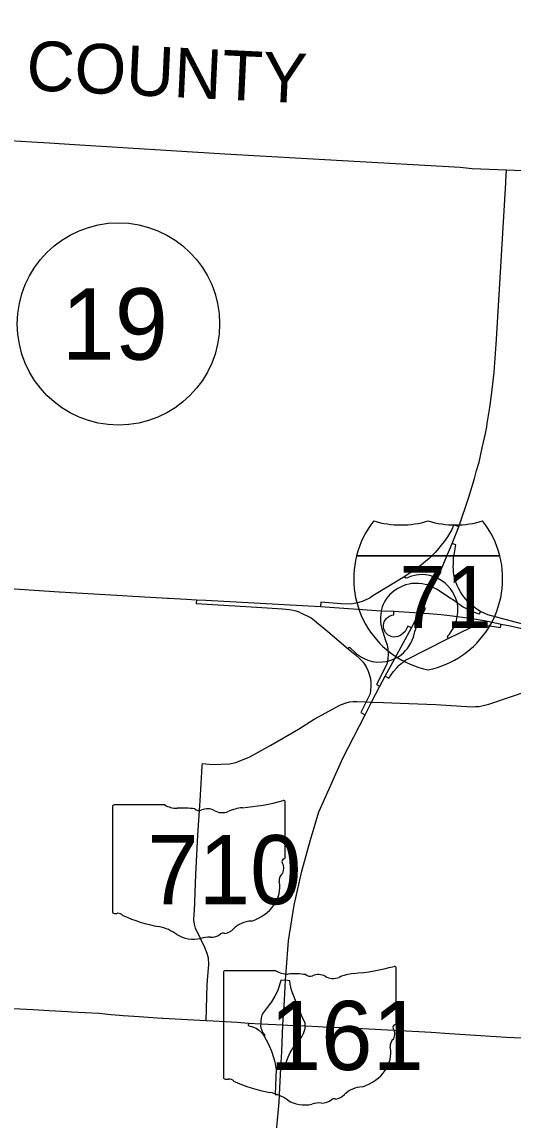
# Model space of a CAD drawing. Extents: x -1146 to -445, y -1283 to -822.
# Drawn here: x -887.8 to -863.1, y -948.4 to -893.1 of the extents above; entities that cross this region are included whole.
import ezdxf

# ---------------------------------------------------------------- set-up
doc = ezdxf.new("R2010")
doc.units = 0
for name, color, linetype in [('Default', 7, 'Continuous'), ('GM_X_Adjacent_County_Text', 7, 'Continuous'), ('GM_X_County', 7, 'Continuous'), ('GM_X_Interchange_Ramps', 7, 'Continuous'), ('GM_X_Interstate_Route', 7, 'Continuous'), ('GM_X_Interstate_Shield', 7, 'Continuous'), ('GM_X_State_Route', 7, 'Continuous'), ('GM_X_State_Shield', 7, 'Continuous')]:
    doc.layers.add(name, color=color, linetype=linetype)

msp = doc.modelspace()

# ---------------------------------------------------------------- linework, layer by layer
at = {"layer": 'Default'}
msp.add_circle((-882.968, -908.344), 5.094, dxfattribs=at)
at = {"layer": 'GM_X_County'}
msp.add_lwpolyline([(-889, -899.078), (-887.326, -899.166), (-886.456, -899.216), (-885.188, -899.314), (-877.604, -899.779), (-865.764, -900.453), (-865.165, -900.518), (-863.427, -900.578), (-862.623, -900.623)], dxfattribs=at)
at = {"layer": 'GM_X_Interchange_Ramps'}
for points in [[(-865.828, -918.558), (-866.078, -918.459), (-866.204, -918.728), (-866.401, -919.059), (-866.562, -919.295), (-866.716, -919.488), (-866.846, -919.654), (-867, -919.835), (-867.177, -920.012), (-867.326, -920.158), (-867.516, -920.315), (-867.712, -920.481), (-868.075, -920.737), (-868.547, -921.067), (-870.161, -922.04), (-870.296, -922.131), (-870.387, -922.183), (-870.51, -922.246), (-870.586, -922.279), (-870.696, -922.322), (-870.809, -922.358), (-870.911, -922.385), (-871.009, -922.406), (-871.103, -922.421), (-871.258, -922.453), (-871.76, -922.444), (-872.777, -922.362), (-872.795, -922.571)], [(-862.612, -923.457), (-863.25, -923.291), (-864.377, -922.994), (-864.744, -922.819), (-864.87, -922.744), (-864.977, -922.67), (-865.062, -922.607), (-865.162, -922.525), (-865.285, -922.414), (-865.377, -922.32), (-865.483, -922.202), (-865.57, -922.093), (-865.66, -921.966), (-865.746, -921.831), (-865.827, -921.684), (-865.908, -921.511), (-865.958, -921.387), (-866.005, -921.251), (-866.05, -921.094), (-866.077, -920.976), (-866.094, -920.823), (-866.098, -920.697), (-866.113, -920.571), (-866.106, -920.433), (-866.106, -920.288), (-866.09, -920.126), (-866.07, -919.973), (-865.973, -919.464), (-866.167, -919.406)], [(-866.359, -924.181), (-866.399, -924.069), (-866.304, -923.974), (-866.209, -923.84), (-866.113, -923.689), (-865.996, -923.46), (-865.946, -923.281), (-865.912, -923.079), (-865.873, -922.873), (-865.879, -922.61), (-865.901, -922.403), (-866.002, -922.123), (-866.147, -921.833), (-866.242, -921.682), (-866.415, -921.508), (-866.522, -921.391), (-866.728, -921.245), (-866.907, -921.145), (-867.086, -921.078), (-867.282, -921.011), (-867.5, -920.972), (-867.673, -920.96), (-867.841, -920.972), (-867.981, -920.988), (-868.256, -921.067), (-868.421, -921.123), (-868.496, -921.154), (-868.547, -921.067)], [(-864.744, -922.819), (-864.822, -922.956), (-865.074, -922.856), (-865.208, -922.794), (-865.426, -922.694), (-865.605, -922.604), (-865.717, -922.537), (-865.901, -922.403), (-866.055, -922.295), (-866.262, -922.148), (-866.958, -921.698), (-867.154, -921.597), (-867.284, -921.543), (-867.428, -921.485), (-867.525, -921.464), (-867.669, -921.428), (-867.838, -921.41), (-868.003, -921.41), (-868.194, -921.424), (-868.338, -921.446), (-868.518, -921.489), (-868.734, -921.579), (-868.899, -921.662), (-869.036, -921.744), (-869.187, -921.863), (-869.32, -921.982), (-869.475, -922.176), (-869.558, -922.313), (-869.644, -922.478), (-869.687, -922.59), (-869.734, -922.784), (-869.756, -922.964), (-869.774, -923.122), (-869.774, -923.327), (-869.764, -923.474), (-869.73, -923.637), (-869.519, -924.279), (-869.446, -924.508), (-869.407, -924.72), (-869.384, -924.983), (-869.407, -925.212), (-869.422, -925.322), (-869.463, -925.486), (-869.969, -926.498), (-869.804, -926.591)], [(-879.041, -922.231), (-879.057, -922.417), (-876.007, -922.607), (-874.715, -922.686), (-874.369, -922.726), (-874.164, -922.765), (-874.03, -922.796), (-873.888, -922.847), (-873.764, -922.902), (-873.494, -923.025), (-873.266, -923.151), (-873.092, -923.277), (-872.431, -923.836), (-871.403, -924.703), (-871.048, -924.998), (-870.82, -925.203), (-870.682, -925.345), (-870.584, -925.479), (-870.477, -925.644), (-870.391, -925.825), (-870.336, -925.983), (-870.28, -926.215), (-870.253, -926.396), (-870.253, -926.589), (-870.269, -926.782), (-870.299, -926.967), (-870.492, -927.382), (-870.756, -927.913), (-870.546, -928.025)], [(-871.403, -924.703), (-871.334, -924.623), (-870.974, -924.957), (-870.726, -925.127), (-870.555, -925.216), (-870.411, -925.275), (-870.192, -925.342), (-869.958, -925.375), (-869.673, -925.364), (-869.495, -925.342), (-869.422, -925.322), (-869.243, -925.272), (-869.052, -925.189), (-868.824, -925.075), (-868.62, -924.905), (-868.509, -924.797), (-868.422, -924.684), (-868.241, -924.413), (-868.119, -924.115), (-868.037, -923.825), (-867.932, -923.513), (-867.735, -923.132), (-867.627, -922.907), (-867.5, -922.656), (-867.675, -922.606)], [(-868.218, -923.643), (-868.398, -923.559), (-868.536, -923.835), (-868.744, -924.012), (-868.803, -924.048), (-868.904, -924.09), (-869.002, -924.11), (-869.105, -924.112), (-869.204, -924.096), (-869.306, -924.059), (-869.386, -924.013), (-869.469, -923.942), (-869.515, -923.887), (-869.563, -923.809), (-869.605, -923.701), (-869.623, -923.602), (-869.624, -923.519), (-869.609, -923.421), (-869.583, -923.341), (-869.541, -923.259), (-869.479, -923.177), (-869.422, -923.123), (-869.375, -923.088), (-869.317, -923.054), (-869.195, -923.013), (-869.107, -923.001), (-869.097, -922.805)], [(-869.534, -926.081), (-869.358, -926.189), (-869.115, -925.84), (-868.957, -925.669), (-868.826, -925.525), (-868.661, -925.387), (-868.523, -925.282), (-866.359, -924.181), (-865.219, -923.627), (-865.029, -923.577), (-864.911, -923.543), (-864.805, -923.532), (-864.67, -923.514), (-864.473, -923.527), (-864.268, -923.54), (-863.727, -923.639), (-863.692, -923.463)], [(-874.554, -941.397), (-874.79, -941.404), (-874.875, -941.691), (-874.967, -941.942), (-875.102, -942.204), (-875.269, -942.476), (-875.531, -942.831), (-875.676, -943.039), (-875.742, -943.16), (-875.785, -943.298), (-875.798, -943.44), (-875.805, -943.584)], [(-873.568, -943.696), (-873.562, -943.547), (-873.661, -943.358), (-873.811, -943.006), (-874.016, -942.504), (-874.177, -942.115), (-874.254, -941.902), (-874.293, -941.744), (-874.324, -941.599), (-874.343, -941.429), (-874.554, -941.397)], [(-876.427, -943.552), (-876.436, -943.682), (-876.215, -943.736), (-876.037, -943.814), (-875.893, -943.914), (-875.755, -944.052), (-875.63, -944.217), (-875.435, -944.575), (-875.259, -944.969), (-875.153, -945.286), (-875.088, -945.507), (-875.055, -945.701), (-875.032, -945.911), (-875.047, -946.254), (-875.08, -947.157), (-874.865, -947.176)], [(-875.805, -943.584), (-875.81, -943.687), (-875.801, -943.782), (-875.772, -943.87), (-875.731, -943.966), (-875.681, -944.059), (-875.602, -944.18), (-875.63, -944.217)], [(-874.795, -945.801), (-874.595, -945.813), (-874.503, -945.49), (-874.424, -945.267), (-874.328, -945.041), (-874.212, -944.844), (-874.06, -944.633), (-873.887, -944.43), (-873.743, -944.239), (-873.658, -944.078), (-873.623, -943.981), (-873.574, -943.821), (-873.568, -943.696)]]:
    msp.add_lwpolyline(points, dxfattribs=at)
at = {"layer": 'GM_X_Interstate_Route'}
for points in [[(-863.944, -909.369), (-863.925, -909.108), (-863.765, -906.3), (-863.467, -901.243), (-863.462, -901.161), (-863.427, -900.578)], [(-864.425, -913.524), (-864.396, -913.36), (-864.262, -912.549), (-864.165, -911.794), (-864.049, -910.778), (-863.944, -909.369)], [(-865.828, -918.558), (-865.318, -917.062), (-865.042, -916.125), (-864.932, -915.723), (-864.814, -915.298), (-864.648, -914.581), (-864.483, -913.864), (-864.425, -913.524)], [(-867.828, -922.893), (-867.675, -922.606), (-867.154, -921.597), (-866.907, -921.145), (-866.665, -920.587), (-866.167, -919.406), (-865.828, -918.558)], [(-890.488, -921.554), (-889.219, -921.625), (-885.958, -921.83)], [(-885.958, -921.83), (-885.941, -921.831), (-884.492, -921.915)], [(-884.492, -921.915), (-882.76, -922.017)], [(-882.76, -922.017), (-882.242, -922.047), (-880.761, -922.131), (-880.496, -922.151)], [(-880.496, -922.151), (-880.456, -922.154), (-879.546, -922.203), (-879.041, -922.231)], [(-879.041, -922.231), (-878.573, -922.257), (-872.795, -922.571)], [(-872.795, -922.571), (-869.734, -922.784), (-869.097, -922.805), (-867.828, -922.893)], [(-870.229, -927.397), (-869.804, -926.591), (-869.534, -926.081), (-869.052, -925.189), (-868.218, -923.643), (-867.828, -922.893)], [(-867.828, -922.893), (-867.627, -922.907), (-867.321, -922.928), (-866.723, -922.979), (-866.141, -923.046), (-865.912, -923.079), (-865.252, -923.169), (-864.561, -923.286), (-864.394, -923.32)], [(-864.394, -923.32), (-863.924, -923.415), (-863.692, -923.463), (-863.24, -923.549), (-863.169, -923.566)], [(-863.169, -923.566), (-862.813, -923.649), (-860.593, -924.234), (-858.566, -924.759), (-857.841, -924.971)], [(-870.546, -928.025), (-870.229, -927.397)], [(-874.537, -941.134), (-874.525, -940.948), (-874.402, -939.41), (-874.115, -937.622), (-873.733, -935.9), (-873.302, -934.318), (-872.872, -932.907), (-872.347, -931.723), (-872.232, -931.463), (-871.678, -930.208), (-870.546, -928.025)], [(-874.694, -943.642), (-874.606, -942.398), (-874.554, -941.397), (-874.537, -941.134)], [(-875.331, -954.149), (-875.316, -953.973), (-875.274, -953.484), (-875.171, -951.599), (-875.053, -949.514), (-874.883, -947.533), (-874.865, -947.176), (-874.795, -945.801), (-874.743, -945.009), (-874.694, -943.642)]]:
    msp.add_lwpolyline(points, dxfattribs=at)
at = {"layer": 'GM_X_Interstate_Shield'}
for p, q in [((-870.98, -920.021), (-863.766, -920.021)), ((-863.766, -920.021), (-870.98, -920.021)), ((-863.766, -920.021), (-870.98, -920.021))]:
    msp.add_line(p, q, dxfattribs=at)
for centre, start, end in [((-866.436, -921.171), 141.669, 165.8066), ((-868.743, -913.78), 253.0091, 286.9909), ((-866.003, -913.78), 253.0091, 286.9909), ((-868.311, -921.171), 14.1934, 38.331), ((-866.436, -921.171), 165.8066, 258.463), ((-868.311, -921.171), 281.537, 14.1934)]:
    msp.add_arc(centre, 4.688, start, end, dxfattribs=at)
at = {"layer": 'GM_X_State_Route'}
for points in [[(-867.897, -927.478), (-866.981, -927.517), (-865.689, -927.59), (-865.153, -927.621), (-864.988, -927.618), (-864.818, -927.605), (-864.673, -927.582), (-864.317, -927.495), (-862.285, -926.801), (-862.241, -926.786), (-860.805, -926.288), (-860.536, -926.18), (-860.158, -926.073), (-859.951, -926.044), (-859.423, -926.051), (-858.896, -926.073), (-858.553, -926.087), (-858.411, -926.065)], [(-871.733, -927.509), (-871.499, -927.426), (-871.328, -927.373), (-871.154, -927.365), (-870.959, -927.356), (-870.492, -927.382), (-870.229, -927.397)], [(-870.229, -927.397), (-869.615, -927.417)], [(-878.752, -930.616), (-878.744, -930.485), (-878.234, -930.535), (-877.382, -930.491), (-877.051, -930.423), (-876.347, -930.152), (-875.442, -929.646), (-875.296, -929.561), (-873.903, -928.754), (-873.111, -928.251), (-871.791, -927.529), (-871.733, -927.509)], [(-869.615, -927.417), (-868.34, -927.459), (-867.897, -927.478)], [(-878.547, -943.418), (-878.5, -941.634), (-878.481, -941.409), (-878.413, -940.592), (-878.441, -940.286), (-878.495, -940.05), (-878.623, -939.753), (-879.088, -938.777), (-879.147, -938.576), (-879.17, -938.351), (-879.154, -938.05), (-879.147, -937.909), (-879.066, -936.07), (-878.963, -934.095), (-878.873, -932.592), (-878.86, -932.367), (-878.752, -930.616), (-878.752, -930.616)], [(-896.201, -942.368), (-895.832, -942.39), (-894.745, -942.457), (-893.343, -942.526), (-891.541, -942.631), (-890.526, -942.687), (-889.734, -942.737), (-888.271, -942.817), (-887.262, -942.874), (-886.455, -942.924), (-885.522, -942.97)], [(-885.522, -942.97), (-885.328, -942.98), (-883.948, -943.058), (-883.35, -943.116), (-882.917, -943.162), (-882.731, -943.173)], [(-882.731, -943.173), (-881.932, -943.218), (-881.235, -943.271), (-880.761, -943.307)], [(-880.761, -943.307), (-880.74, -943.309), (-878.547, -943.418)], [(-878.547, -943.418), (-878.199, -943.436), (-876.992, -943.515)], [(-876.992, -943.515), (-876.427, -943.552), (-875.805, -943.584), (-874.694, -943.642)], [(-874.694, -943.642), (-874.694, -943.642), (-874.444, -943.654)], [(-874.444, -943.654), (-873.568, -943.696), (-872.919, -943.732)], [(-872.919, -943.732), (-872.667, -943.746), (-871.248, -943.798), (-870.354, -943.844), (-867.222, -944.02), (-866.293, -944.081), (-863.431, -944.259), (-862.283, -944.317), (-859.466, -944.485), (-858.806, -944.532), (-857.647, -944.608)]]:
    msp.add_lwpolyline(points, dxfattribs=at)
at = {"layer": 'GM_X_State_Shield'}
for p, q in [((-883.267, -932.658), (-883.267, -937.941)), ((-880.633, -932.567), (-883.182, -932.567)), ((-874.566, -935.199), (-874.566, -932.436)), ((-874.567, -935.199), (-874.566, -935.199)), ((-877.679, -941.007), (-877.679, -946.29)), ((-875.045, -940.916), (-877.594, -940.916)), ((-868.978, -943.548), (-868.978, -940.785)), ((-868.979, -943.548), (-868.978, -943.548))]:
    msp.add_line(p, q, dxfattribs=at)
for centre, major_axis, start_param, end_param in [((-877.666, -925.364), (9.227, 0), 4.814394, 5.042369), ((-874.663, -932.424), (0.0969, 0), 6.141152, 7.989035), ((-883.168, -932.646), (0.101, 0), 1.712693, 3.28349), ((-880.027, -931.953), (0.978, 0), 4.042523, 4.731795), ((-879.702, -935.533), (3.51, 0), 1.404758, 1.657858), ((-878.906, -932.619), (0.282, 0), 3.836095, 5.185415), ((-878.491, -933.23), (0.586, 0), 0.950623, 2.079405), ((-877.735, -932.392), (0.705, 0), 4.081561, 5.145723), ((-876.489, -934.18), (1.856, 0), 1.699011, 2.107814), ((-874.589, -935.402), (0.15, 0), 1.883978, 3.671073), ((-875.542, -935.752), (0.9, 0), 5.934695, 6.695948), ((-874.67, -935.21), (0.104, 0), 5.05454, 6.418171), ((-874.219, -936.356), (0.655, 0), 2.387724, 3.262537), ((-877.149, -936.708), (2.308, 0), 5.101752, 6.440018), ((-883.167, -937.952), (0.102, 0), 3.00124, 4.508301), ((-883.151, -937.412), (0.776, 0), 4.665946, 4.897461), ((-882.992, -938.246), (0.28, 0), 0.519207, 1.627899), ((-879.459, -933.499), (6.663, 0), 4.195997, 4.488961), ((-876.176, -939.424), (1.264, 0), 1.647645, 2.488434), ((-881.446, -940.314), (2.085, 0), 0.823519, 1.323587), ((-877.692, -939.179), (0.198, 0), 1.147584, 2.315152), ((-877.777, -938.453), (0.746, 0), 4.937069, 5.64225), ((-879.191, -938.272), (1.323, 0), 4.026481, 4.996735), ((-878.427, -940.098), (1.087, 0), 1.495662, 1.94098), ((-878.33, -938.667), (0.705, 0), 4.691044, 5.507374), ((-877.58, -940.995), (0.101, 0), 1.712693, 3.28349), ((-874.439, -940.302), (0.978, 0), 4.042523, 4.731795), ((-874.114, -943.882), (3.51, 0), 1.404758, 1.657858), ((-873.318, -940.968), (0.282, 0), 3.836095, 5.185415), ((-872.904, -941.579), (0.586, 0), 0.950623, 2.079405), ((-872.147, -940.741), (0.705, 0), 4.081561, 5.145723), ((-870.901, -942.529), (1.856, 0), 1.699011, 2.107814), ((-872.078, -933.713), (9.227, 0), 4.814394, 5.042369), ((-869.075, -940.773), (0.0969, 0), 6.141152, 7.989035), ((-869.001, -943.751), (0.15, 0), 1.883978, 3.671073), ((-869.954, -944.101), (0.9, 0), 5.934695, 6.695948), ((-869.082, -943.559), (0.104, 0), 5.05454, 6.418171), ((-868.631, -944.705), (0.655, 0), 2.387724, 3.262537), ((-871.561, -945.057), (2.308, 0), 5.101752, 6.440018), ((-877.579, -946.301), (0.102, 0), 3.00124, 4.508301), ((-877.563, -945.761), (0.776, 0), 4.665946, 4.897461), ((-877.404, -946.595), (0.28, 0), 0.519207, 1.627899), ((-873.871, -941.848), (6.663, 0), 4.195997, 4.488961), ((-875.858, -948.663), (2.085, 0), 0.823519, 1.323587), ((-872.189, -946.802), (0.746, 0), 4.937069, 5.64225), ((-870.588, -947.773), (1.264, 0), 1.647645, 2.488434), ((-873.603, -946.621), (1.323, 0), 4.026481, 4.996735), ((-872.839, -948.447), (1.087, 0), 1.495662, 1.94098), ((-872.742, -947.016), (0.705, 0), 4.691044, 5.507374), ((-872.104, -947.528), (0.198, 0), 1.147584, 2.315152)]:
    msp.add_ellipse(centre, major_axis=major_axis, ratio=0.8, start_param=start_param, end_param=end_param, dxfattribs=at)

# ---------------------------------------------------------------- texts
at = {"layer": 'Default'}
msp.add_text('19', height=3.6, dxfattribs=at).set_placement((-885.832, -910.144))
at = {"layer": 'GM_X_Adjacent_County_Text'}
msp.add_text('DELAWARE COUNTY', height=2.5, rotation=357.2562, dxfattribs=at).set_placement((-907.313, -895.62))
at = {"layer": 'GM_X_Interstate_Shield'}
msp.add_text('71', height=3.125, dxfattribs=at).set_placement((-868.817, -923.654))
at = {"layer": 'GM_X_State_Shield'}
for s, p in [('710', (-881.517, -937.568)), ('161', (-875.353, -945.917))]:
    msp.add_text(s, height=3.4805, dxfattribs=at).set_placement(p)

doc.saveas('drawing.dxf')
